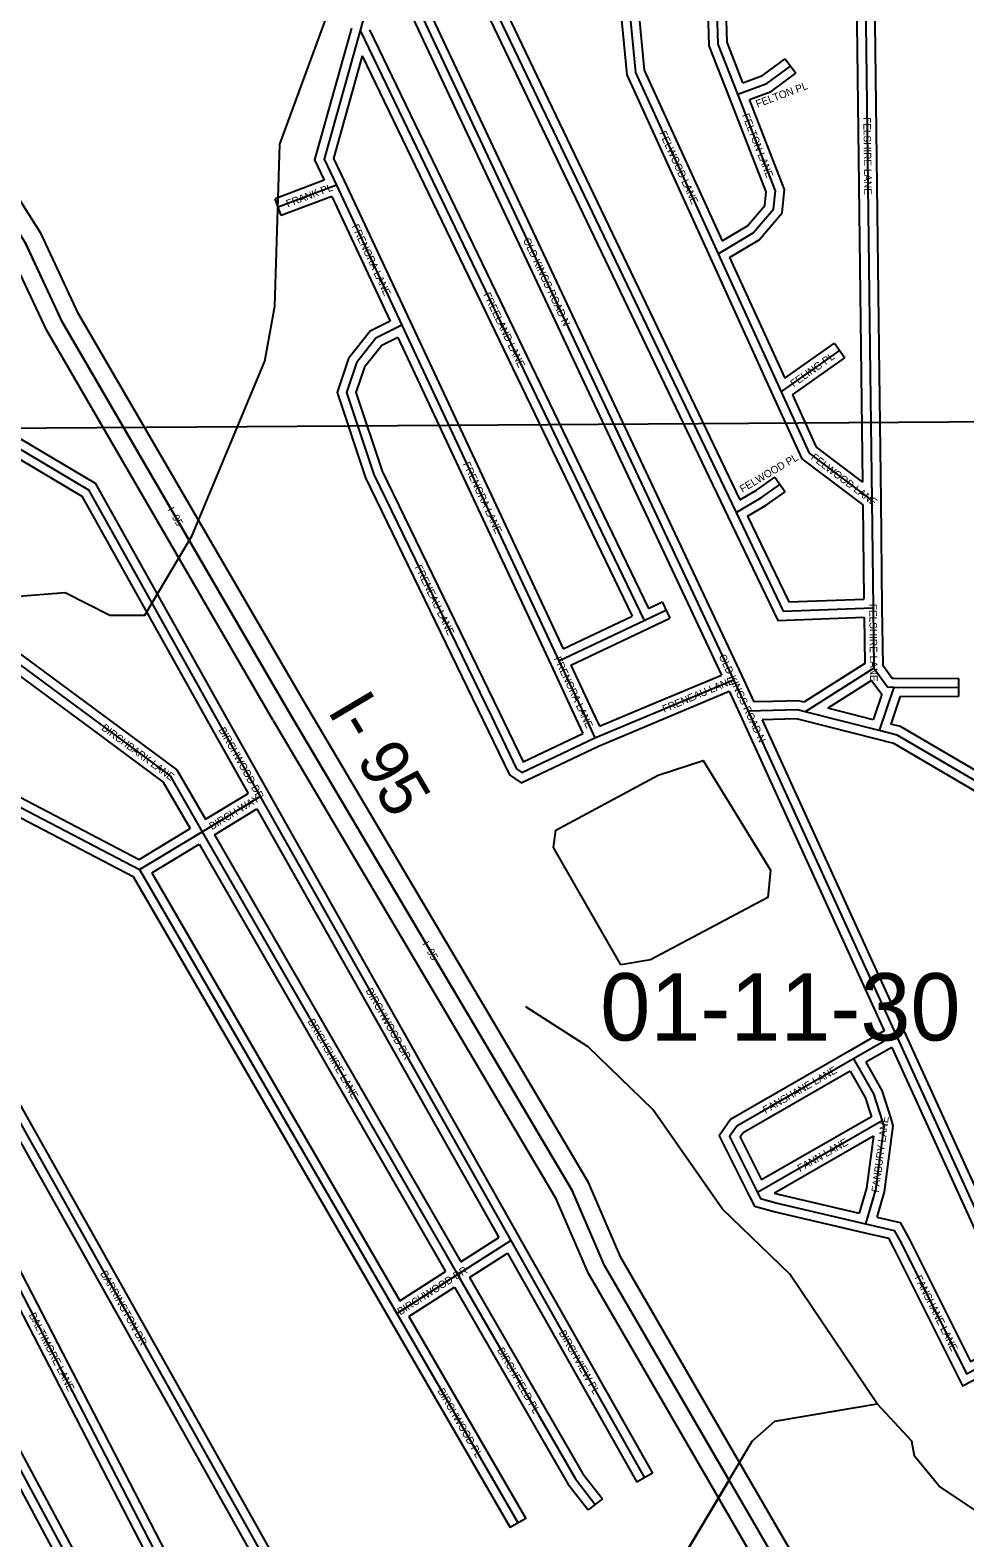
# Model space of a CAD drawing. Extents: x 457167 to 656239, y 1787309 to 1969297.
# Drawn here: x 580059 to 583184, y 1904923 to 1909965 of the extents above; entities that cross this region are included whole.
import ezdxf

# ---------------------------------------------------------------- set-up
doc = ezdxf.new("R2010")
doc.units = 0
for name, color, linetype in [('Level 1', 7, 'Continuous'), ('Level 13', 7, 'Continuous'), ('Level 14', 7, 'Continuous'), ('Level 19', 7, 'Continuous'), ('Level 2', 7, 'Continuous'), ('Level 31', 7, 'Continuous'), ('Level 32', 7, 'Continuous'), ('Level 34', 7, 'Continuous'), ('Level 5', 7, 'Continuous'), ('Level 7', 7, 'Continuous'), ('Level 8', 7, 'Continuous')]:
    doc.layers.add(name, color=color, linetype=linetype)

msp = doc.modelspace()

# ---------------------------------------------------------------- linework, layer by layer
at = {"layer": 'Level 1'}
msp.add_line((579742.085, 1908632.671), (585074.96, 1908666.844), dxfattribs=at)
at = {"layer": 'Level 13'}
msp.add_line((584688.869, 1901162.621), (582396.2, 1905115.545), dxfattribs=at)
for points in [[(580924.16, 1907685.826), (580167.749, 1908987.76), (580043.06, 1909254.566), (579826.985, 1909596.836), (579818.524, 1909655.037), (579585.659, 1910022.435), (579569.285, 1910097.379), (579444.398, 1910264.186), (578820.866, 1911373.871), (578330.566, 1912191.644)], [(582396.2, 1905115.545), (581979.923, 1905833.48), (581872.025, 1906083.882), (580924.16, 1907685.826)]]:
    msp.add_lwpolyline(points, dxfattribs=at)
at = {"layer": 'Level 14'}
for p, q in [((584740.772, 1901192.724), (582448.103, 1905145.647)), ((584636.968, 1901132.518), (582344.298, 1905085.441))]:
    msp.add_line(p, q, dxfattribs=at)
for points in [[(580976.04, 1907715.967), (580220.974, 1909015.588), (580095.816, 1909283.397), (579884.528, 1909618.086), (579876.058, 1909676.342), (579642.014, 1910045.601), (579625.124, 1910122.912), (579494.782, 1910297.004), (578872.76, 1911404.001), (578385.413, 1912216.85)], [(580872.28, 1907655.684), (580114.525, 1908959.931), (579990.304, 1909225.736), (579769.444, 1909575.588), (579760.99, 1909633.732), (579529.304, 1909999.269), (579513.448, 1910071.846), (579394.013, 1910231.37), (578768.972, 1911343.741), (578275.722, 1912166.436)], [(582448.106, 1905145.641), (582033.616, 1905860.495), (581925.613, 1906111.142), (580976.04, 1907715.967)], [(582344.294, 1905085.448), (581926.23, 1905806.465), (581818.437, 1906056.622), (580872.522, 1907655.271)]]:
    msp.add_lwpolyline(points, dxfattribs=at)
at = {"layer": 'Level 31'}
for p, q in [((582850.693, 1910215.451), (582866.854, 1908903.396)), ((581287.445, 1910184.404), (582275.584, 1908080.924)), ((581599.648, 1910063.042), (582419.162, 1908351.551)), ((581162.4, 1909963.198), (582112.337, 1907990.703)), ((581083.161, 1909445.896), (580888.485, 1909372.836)), ((581083.161, 1909445.896), (581302.174, 1908977.807)), ((582359.534, 1909216.775), (582569.995, 1908755.256)), ((581302.174, 1908977.807), (581826.939, 1907856.001)), ((582569.995, 1908755.256), (582766.072, 1908893.414)), ((582866.854, 1908903.396), (582873.154, 1908392.102)), ((582569.995, 1908755.256), (582663.359, 1908550.34)), ((582663.359, 1908550.34), (582873.154, 1908392.102)), ((579233.984, 1908427.137), (580282.943, 1907651.5)), ((582873.154, 1908392.102), (582877.213, 1908033.179)), ((582275.584, 1908080.924), (582411.058, 1907792.648)), ((581826.939, 1907856.001), (582112.337, 1907990.703)), ((582112.337, 1907990.703), (582184.879, 1908025.468)), ((582877.213, 1908033.179), (582879.674, 1907830.625)), ((581826.939, 1907856.001), (581911.132, 1907675.829)), ((582144.141, 1907680.816), (582411.058, 1907792.648)), ((582411.058, 1907792.648), (582460.119, 1907687.821)), ((582879.674, 1907830.625), (582650.836, 1907684.896)), ((582946.621, 1907767.946), (582897.699, 1907622.586)), ((582946.621, 1907767.946), (583163.087, 1907766.063)), ((582542.452, 1907689.475), (582460.119, 1907687.821)), ((582460.119, 1907687.821), (582953.228, 1906605.732)), ((582897.699, 1907622.586), (582650.836, 1907684.896)), ((580682.528, 1907661.227), (580828.54, 1907402.016)), ((581911.132, 1907675.829), (581947.214, 1907598.301)), ((581947.214, 1907598.301), (582144.141, 1907680.816)), ((580634.715, 1907284.228), (580828.54, 1907402.016)), ((580828.54, 1907402.016), (581666.019, 1905917.386)), ((580002.654, 1907378.254), (580424.976, 1907157.382)), ((580424.976, 1907157.382), (580634.715, 1907284.228)), ((580634.715, 1907284.228), (581488.409, 1905803.56)), ((580424.976, 1907157.382), (581284.698, 1905673.424)), ((582953.228, 1906605.732), (582812.247, 1906524.556)), ((582953.228, 1906605.732), (583264.997, 1905921.47)), ((579632.132, 1906511.732), (580614.015, 1904611.5)), ((580389.619, 1904475.23), (579385.429, 1906344.969)), ((582907.519, 1906317.091), (582491.254, 1906078.278)), ((581488.409, 1905803.56), (581666.019, 1905917.386)), ((581666.019, 1905917.386), (582113.61, 1905124.109)), ((581284.698, 1905673.424), (581488.409, 1905803.56)), ((581284.698, 1905673.424), (581690.507, 1904972.23))]:
    msp.add_line(p, q, dxfattribs=at)
for points in [[(582045.579, 1910215.239), (582083.255, 1909823.156), (582359.534, 1909216.775)], [(582424.804, 1909750.471), (582359.34, 1909917.878), (582350.396, 1910214.992)], [(581287.445, 1910184.404), (581192.818, 1910072.957), (581162.4, 1909963.198)], [(581162.4, 1909963.198), (581042.017, 1909533.254), (581083.161, 1909445.896)], [(582424.804, 1909750.471), (582521.821, 1909786.643), (582601.399, 1909844.667)], [(582359.534, 1909216.775), (582476.647, 1909287.088), (582544.824, 1909365.862), (582550.986, 1909427.67), (582424.804, 1909750.471)], [(581302.174, 1908977.807), (581215.31, 1908934.346), (581150.301, 1908852.658), (581117.042, 1908753.088), (581208.35, 1908478.716), (581601.194, 1907669.181)], [(579559.062, 1908841.015), (580254.652, 1908427.935), (580682.528, 1907661.227)], [(582419.162, 1908351.551), (582504.131, 1908401.564), (582565.884, 1908445.441)], [(582419.162, 1908351.551), (582577.123, 1908021.776), (582877.213, 1908033.179)], [(582879.674, 1907830.625), (582925.959, 1907768.351), (582946.621, 1907767.946)], [(582650.836, 1907684.896), (582624.784, 1907691.493), (582542.452, 1907689.475)], [(580282.943, 1907651.5), (580527.335, 1907470.632), (580634.715, 1907284.228)], [(581601.194, 1907669.181), (581685.714, 1907494.825), (581703.174, 1907482.79), (581947.214, 1907598.301)], [(583394.638, 1907351.782), (582958.065, 1907607.557), (582897.699, 1907622.586)], [(579632.132, 1906511.732), (579799.889, 1906625.205), (579855.175, 1906612.727), (580869.682, 1904805.89), (580875.014, 1904770.606), (580614.015, 1904611.5)], [(582812.247, 1906524.556), (582421.759, 1906299.875), (582397.849, 1906264.65), (582491.254, 1906078.278)], [(582812.247, 1906524.556), (582879.088, 1906407.331), (582907.519, 1906317.091)], [(582907.519, 1906317.091), (582913.204, 1906298.171), (582885.131, 1906086.586), (582851.846, 1905973.196)], [(582491.254, 1906078.278), (582501.386, 1906057.895), (582556.985, 1906042.511), (582851.846, 1905973.196)], [(582851.846, 1905973.196), (582948.439, 1905950.823), (582971.564, 1905909.321), (583190.045, 1905471.792), (583349.79, 1905555.115)], [(581488.409, 1905803.56), (581882.175, 1905120.211), (581948.762, 1905034.621)]]:
    msp.add_lwpolyline(points, dxfattribs=at)
at = {"layer": 'Level 32'}
for p, q in [((582880.691, 1910215.819), (582896.853, 1908903.765)), ((581314.599, 1910197.159), (582302.737, 1908093.679)), ((582821.06, 1910185.422), (582836.856, 1908903.026)), ((581280.125, 1910129.429), (582248.431, 1908068.167)), ((581558.627, 1910079.246), (582392.104, 1908338.593)), ((581640.669, 1910046.836), (582432.107, 1908393.981)), ((581194.324, 1909966.054), (582126.374, 1908030.698)), ((581169.86, 1909878.568), (582072.189, 1908004.926)), ((582583.723, 1909868.908), (582619.074, 1909820.426)), ((581042.157, 1909462.55), (580877.945, 1909400.923)), ((581110.335, 1909458.611), (581329.347, 1908990.521)), ((580899.027, 1909344.748), (580877.945, 1909400.923)), ((581067.741, 1909408.065), (580899.027, 1909344.748)), ((581067.741, 1909408.064), (581262.617, 1908991.561)), ((582332.239, 1909204.327), (582542.699, 1908742.809)), ((582397.949, 1909204.844), (582582.284, 1908800.615)), ((581329.348, 1908990.518), (581841.357, 1907895.98)), ((581288.053, 1908937.195), (581799.764, 1907843.289)), ((582582.284, 1908800.615), (582748.792, 1908917.938)), ((582748.792, 1908917.938), (582783.352, 1908868.89)), ((582836.856, 1908903.026), (582842.403, 1908452.872)), ((582896.853, 1908903.766), (582903.153, 1908392.471)), ((582607.61, 1908745.059), (582783.352, 1908868.89)), ((582542.695, 1908742.818), (582639.215, 1908530.971)), ((582607.61, 1908745.058), (582687.504, 1908569.706)), ((582687.504, 1908569.706), (582842.403, 1908452.872)), ((582639.215, 1908530.971), (582843.323, 1908377.024)), ((582548.508, 1908469.897), (582583.26, 1908420.985)), ((579276.656, 1908432.895), (580300.779, 1907675.622)), ((582903.153, 1908392.441), (582907.212, 1908033.517)), ((579239.54, 1908385.717), (580265.107, 1907627.376)), ((582843.323, 1908377.025), (582846.885, 1908062.049)), ((582302.735, 1908093.683), (582438.209, 1907805.408)), ((582126.374, 1908030.697), (582171.915, 1908052.521)), ((582171.915, 1908052.521), (582197.845, 1907998.413)), ((582248.433, 1908068.163), (582370.592, 1907808.221)), ((581841.358, 1907895.981), (582072.189, 1908004.927)), ((582125.303, 1907963.649), (582197.845, 1907998.413)), ((582847.589, 1908002.031), (582849.474, 1907846.96)), ((582907.212, 1908033.542), (582909.555, 1907840.714)), ((581866.77, 1907841.625), (582125.143, 1907963.572)), ((581799.759, 1907843.3), (581883.954, 1907663.127)), ((581866.77, 1907841.625), (581938.311, 1907688.529)), ((582849.474, 1907846.959), (582645.647, 1907717.156)), ((582132.549, 1907708.486), (582370.592, 1907808.221)), ((582438.229, 1907805.366), (582479.022, 1907718.207)), ((582872.247, 1907790.326), (582725.631, 1907696.958)), ((582872.247, 1907790.326), (582906.836, 1907743.787)), ((582947.208, 1907797.941), (583163.349, 1907796.062)), ((583163.349, 1907796.062), (583162.827, 1907736.063)), ((582155.735, 1907653.146), (582396.094, 1907753.85)), ((582396.094, 1907753.85), (582432.82, 1907675.38)), ((582906.836, 1907743.787), (582878.123, 1907658.468)), ((582968.115, 1907737.756), (582936.508, 1907643.84)), ((582968.115, 1907737.756), (583162.827, 1907736.063)), ((581938.331, 1907688.486), (581962.237, 1907637.121)), ((581962.237, 1907637.122), (582132.548, 1907708.486)), ((582541.849, 1907719.469), (582479.023, 1907718.207)), ((582878.123, 1907658.468), (582725.631, 1907696.958)), ((580656.389, 1907646.502), (580788.157, 1907412.579)), ((580708.667, 1907675.951), (580854.679, 1907416.74)), ((581883.934, 1907663.17), (581907.439, 1907612.665)), ((581959.436, 1907570.892), (582155.736, 1907653.146)), ((582432.82, 1907675.38), (582914.616, 1906618.117)), ((582543.054, 1907659.48), (582506.339, 1907658.742)), ((582506.34, 1907658.742), (582980.529, 1906618.173)), ((582890.359, 1907593.497), (582643.495, 1907655.806)), ((580025.806, 1907400.001), (580423.909, 1907191.796)), ((580645.381, 1907325.814), (580788.157, 1907412.579)), ((580854.67, 1907416.756), (581692.149, 1905932.125)), ((579979.504, 1907356.506), (580403.374, 1907134.824)), ((580675.349, 1907273.815), (580817.638, 1907360.283)), ((580817.637, 1907360.283), (581625.957, 1905927.343)), ((580423.909, 1907191.796), (580594.061, 1907294.7)), ((580465.694, 1907146.946), (580624.028, 1907242.702)), ((580624.028, 1907242.702), (581448.101, 1905813.408)), ((580675.349, 1907273.815), (581498.694, 1905845.783)), ((580403.374, 1907134.823), (581258.739, 1905658.385)), ((580465.694, 1907146.946), (581294.951, 1905715.572)), ((582914.616, 1906618.118), (582797.277, 1906550.556)), ((582980.529, 1906618.171), (583280.244, 1905960.364)), ((582939.609, 1906563.27), (582853.107, 1906513.463)), ((582939.609, 1906563.27), (583237.698, 1905909.03)), ((579671.024, 1906501.818), (580625.889, 1904653.873)), ((579620.974, 1906467.976), (580587.364, 1904597.728)), ((580417.396, 1904486.916), (579424.681, 1906335.289)), ((582871.653, 1906331.101), (582503.854, 1906120.094)), ((580361.844, 1904463.541), (579374.688, 1906301.562)), ((582878.665, 1906265.949), (582547.86, 1906076.165)), ((581498.694, 1905845.783), (581625.957, 1905927.344)), ((581692.147, 1905932.127), (582139.739, 1905138.851)), ((581528.692, 1905793.741), (581655.488, 1905875.001)), ((581655.488, 1905875.001), (582087.483, 1905109.366)), ((581294.95, 1905715.572), (581448.1, 1905813.409)), ((581325.047, 1905663.598), (581478.096, 1905761.37)), ((581258.733, 1905658.396), (581664.541, 1904957.202)), ((581325.047, 1905663.599), (581716.473, 1904987.257)), ((582139.739, 1905138.851), (582087.483, 1905109.366)), ((581972.44, 1905053.041), (581925.084, 1905016.199)), ((581716.473, 1904987.257), (581664.541, 1904957.202))]:
    msp.add_line(p, q, dxfattribs=at)
for points in [[(582018.319, 1910185.291), (582053.873, 1909815.288), (582332.234, 1909204.336)], [(582078.603, 1910185.211), (582112.638, 1909831.026), (582372.903, 1909259.793)], [(582396.863, 1909739.546), (582329.509, 1909911.787), (582321.285, 1910185.015)], [(582441.99, 1909788.896), (582389.17, 1909923.97), (582381.313, 1910185.019)], [(581133.511, 1909971.287), (581010.114, 1909530.581), (581042.156, 1909462.55)], [(581169.86, 1909878.568), (581073.92, 1909535.926), (581110.303, 1909458.679)], [(582441.99, 1909788.896), (582507.477, 1909813.313), (582583.723, 1909868.908)], [(582463.841, 1909733.007), (582536.164, 1909759.972), (582619.074, 1909820.426)], [(582372.903, 1909259.793), (582457.097, 1909310.344), (582515.915, 1909378.303), (582520.418, 1909423.466), (582396.862, 1909739.55)], [(582397.949, 1909204.844), (582496.197, 1909263.833), (582573.733, 1909353.421), (582581.554, 1909431.872), (582463.841, 1909733.007)], [(581262.617, 1908991.561), (581195.961, 1908958.212), (581123.525, 1908867.191), (581085.418, 1908753.106), (581180.504, 1908467.382), (581574.204, 1907656.082)], [(581288.052, 1908937.193), (581234.659, 1908910.481), (581177.077, 1908838.125), (581148.665, 1908753.07), (581236.196, 1908490.05), (581628.184, 1907682.278)], [(579603.749, 1908849.37), (580276.914, 1908449.606), (580708.724, 1907675.846)], [(579566.389, 1908801.771), (580232.39, 1908406.264), (580656.33, 1907646.607)], [(582432.108, 1908393.981), (582487.804, 1908426.765), (582548.508, 1908469.897)], [(582458.119, 1908339.668), (582520.459, 1908376.362), (582583.26, 1908420.985)], [(582392.105, 1908338.59), (582558.576, 1907991.048), (582847.589, 1908002.03)], [(582458.119, 1908339.667), (582595.669, 1908052.503), (582846.885, 1908062.049)], [(582909.555, 1907840.714), (582941.259, 1907798.058), (582947.208, 1907797.941)], [(582645.647, 1907717.157), (582628.161, 1907721.586), (582541.716, 1907719.466)], [(580300.789, 1907675.615), (580550.209, 1907491.027), (580645.381, 1907325.815)], [(581574.198, 1907656.094), (581662.171, 1907474.616), (581700.382, 1907448.276), (581959.436, 1907570.892)], [(581628.189, 1907682.266), (581707.749, 1907518.146), (581907.439, 1907612.665)], [(582643.472, 1907655.813), (582621.407, 1907661.401), (582543.187, 1907659.483)], [(583364.192, 1907404.389), (582969.504, 1907635.626), (582936.508, 1907643.84)], [(580265.096, 1907627.385), (580504.462, 1907450.238), (580594.061, 1907294.701)], [(583364.787, 1907334.501), (582946.628, 1907579.489), (582890.453, 1907593.474)], [(579615.324, 1906536.582), (579793.832, 1906657.327), (579874.799, 1906639.054), (580898.526, 1904815.796), (580907.658, 1904755.37), (580653.498, 1904600.431)], [(579671.024, 1906501.818), (579805.947, 1906593.083), (579835.551, 1906586.401), (580840.838, 1904795.985), (580842.371, 1904785.842), (580625.889, 1904653.873)], [(582797.284, 1906550.561), (582400.814, 1906322.436), (582363.144, 1906266.94), (582464.434, 1906064.836)], [(582801.104, 1906483.532), (582442.704, 1906277.314), (582432.554, 1906262.36), (582503.855, 1906120.094)], [(582801.104, 1906483.532), (582851.438, 1906395.257), (582871.653, 1906331.101)], [(582853.106, 1906513.463), (582906.739, 1906419.405), (582936.252, 1906325.723)], [(582936.252, 1906325.723), (582943.793, 1906300.622), (582914.567, 1906080.351), (582889.587, 1905995.248)], [(582878.665, 1906265.949), (582855.694, 1906092.821), (582831.061, 1906008.9)], [(582547.86, 1906076.165), (582564.421, 1906071.582), (582831.061, 1906008.899)], [(582464.434, 1906064.836), (582480.481, 1906032.551), (582549.55, 1906013.441), (582844.981, 1905943.991)], [(582889.587, 1905995.248), (582968.17, 1905977.047), (582998.1, 1905923.331), (583203.244, 1905512.513), (583335.916, 1905581.714)], [(582845.076, 1905943.97), (582928.709, 1905924.598), (582945.027, 1905895.312), (583176.847, 1905431.071), (583363.664, 1905528.515)], [(581528.692, 1905793.741), (581907.13, 1905136.991), (581972.44, 1905053.041)], [(581478.096, 1905761.37), (581857.22, 1905103.43), (581925.084, 1905016.199)]]:
    msp.add_lwpolyline(points, dxfattribs=at)
at = {"layer": 'Level 5'}
msp.add_lwpolyline([(582033.565, 1906839.591), (581808.907, 1907231.628), (581817.306, 1907289.99), (582159.289, 1907473.026), (582309.409, 1907522.878), (582534.098, 1907155.821), (582525.669, 1907064.148), (582133.636, 1906856.131), (582033.565, 1906839.591)], close=True, dxfattribs=at)
for points in [[(582890.646, 1905371.479), (582599.367, 1905805.268), (582374.511, 1906022.272), (582141.454, 1906355.949), (581924.908, 1906564.593), (581716.663, 1906698.205)], [(581572.482, 1904389.189), (581589.251, 1904480.861), (581664.371, 1904564.163), (581997.924, 1904647.167), (582181.415, 1904755.341), (582473.703, 1905246.854), (582548.833, 1905313.486), (582890.646, 1905371.479)], [(583523.494, 1904695.546), (583223.745, 1905012.652), (583098.763, 1905096.154), (583015.53, 1905196.256), (583007.229, 1905246.306), (582890.646, 1905371.479)]]:
    msp.add_lwpolyline(points, dxfattribs=at)
at = {"layer": 'Level 7'}
msp.add_lwpolyline([(579850.76, 1908059.018), (580175.904, 1908083.701), (580325.897, 1908008.51), (580442.599, 1908008.38), (580601.247, 1908274.987), (580843.623, 1908858.263), (580877.161, 1909041.637), (580894.414, 1909583.461), (581053.26, 1910016.791)], dxfattribs=at)
at = {"layer": 'Level 8'}
msp.add_lwpolyline([(581660.601, 1904558.273), (581994.604, 1904641.277), (582178.605, 1904749.281), (582253.604, 1904876.284), (582396.604, 1905115.291), (581979.588, 1905833.306), (581871.584, 1906084.311), (580924.549, 1907685.345), (580167.522, 1908987.372), (580043.517, 1909254.378)], dxfattribs=at)

# ---------------------------------------------------------------- texts
at = {"layer": 'Level 19'}
msp.add_text('I- 95', height=160, rotation=300.612286, dxfattribs=at).set_placement((581050.691, 1907689.494))
at = {"layer": 'Level 2'}
msp.add_text('01-11-30', height=225, dxfattribs=at).set_placement((581965.329, 1906586.125))
at = {"layer": 'Level 34'}
for s, rotation, p in [('FELTON PL', 20.446314, (582490.865, 1909705.254)), ('FELTON LANE', 291.349964, (582438.757, 1909680.444)), ('FELSHIRE LANE', 270.704931, (582844.867, 1909673.591)), ('FELWOOD LANE', 294.494492, (582161.639, 1909620.974)), ('FRANK PL', 20.569936, (580920.77, 1909371.602)), ('FRENORA LANE', 295.073769, (581133.494, 1909308.827)), ('OLD KINGS ROAD N', 295.161989, (581706.524, 1909262.901)), ('FREELAND LANE', 295.714625, (581573.63, 1909080.495)), ('FELING PL', 35.168217, (582611.896, 1908769.491)), ('FELWOOD PL', 30.480447, (582440.715, 1908417.379)), ('FELWOOD LANE', 322.974536, (582667.566, 1908531.51)), ('FRENORA LANE', 295.069086, (581505.391, 1908513.884)), ('I- 95', 300.155772, (580517.189, 1908361.424)), ('FRENEAU LANE', 295.885467, (581344.643, 1908169.226)), ('FELSHIRE LANE', 270.695275, (582864.557, 1908046.073)), ('FRENORA LANE', 295.045817, (581809.909, 1907862.919)), ('OLD KINGS ROAD N', 295.080378, (582360.784, 1907870.579)), ('FRENEAU LANE', 22.73195, (582179.159, 1907681.936)), ('BIRCHBARK LANE', 323.495797, (580295.549, 1907626.621)), ('BIRCHWOOD DR', 299.391975, (580688.532, 1907625.101)), ('BIRCH WAY', 31.286475, (580667.06, 1907289.259)), ('I- 95', 300.612286, (581369.13, 1906909.255)), ('BIRCHWOOD DR', 299.426903, (581180.219, 1906753.138)), ('BRICHSHIRE LANE', 299.965642, (580985.839, 1906650.205)), ('FANSHANE LANE', 29.914861, (582517.996, 1906340.83)), ('FANBURY LANE', 82.441122, (582896.457, 1906076.929)), ('FANN LANE', 29.842336, (582633.484, 1906145.466)), ('BARRINGTON DR', 299.313042, (580292.779, 1905807.823)), ('BIRCHWOOD DR', 32.570703, (581296.933, 1905666.41)), ('FANSHANE LANE', 296.53495, (583015.379, 1905793.601)), ('BALTIMORE LANE', 297.325767, (580053.846, 1905668.364)), ('BIRCHVIEW PL', 299.432686, (581825.764, 1905608.83)), ('BIRCHFIELD PL', 299.951472, (581619.503, 1905551.021)), ('BIRCHWOOD PL', 300.059264, (581419.989, 1905414.702))]:
    msp.add_text(s, height=25, rotation=rotation, dxfattribs=at).set_placement(p)

doc.saveas('drawing.dxf')
